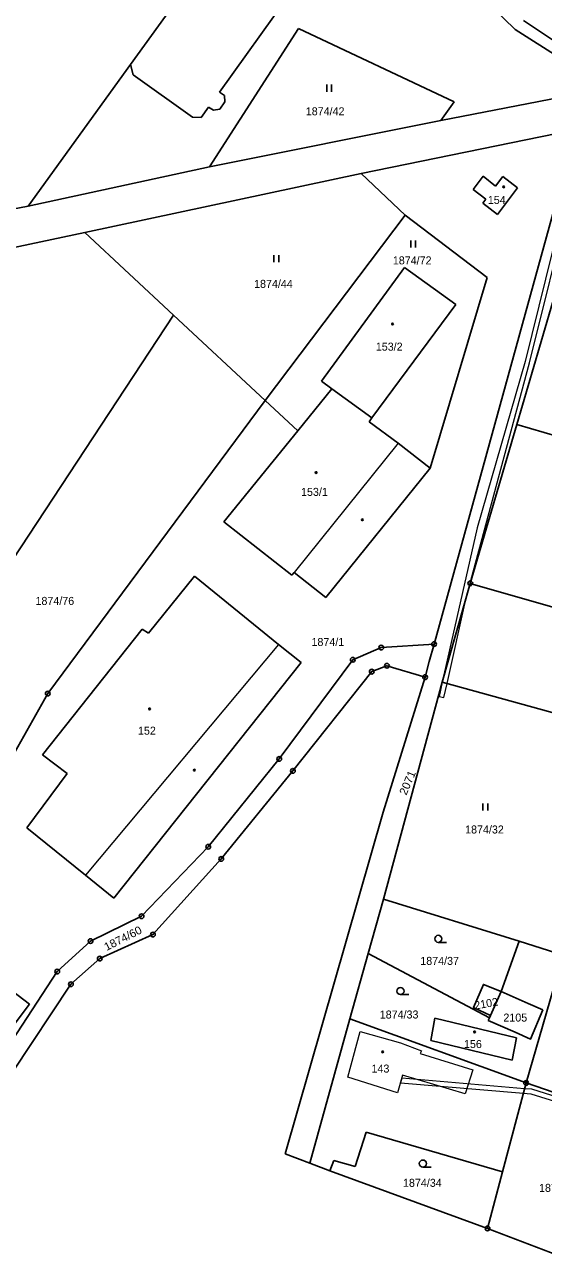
# Model space of a CAD drawing. Extents: x -820420 to -815896, y -1105820 to -1103643.
# Drawn here: x -818234.8 to -818124.5, y -1105443.7 to -1105183.5 of the extents above; entities that cross this region are included whole.
import ezdxf
from ezdxf.enums import TextEntityAlignment as Align

# ---------------------------------------------------------------- set-up
doc = ezdxf.new("R2010")
doc.units = 0
doc.header["$LTSCALE"] = 0.68
for name, color, linetype, lineweight in [('1', 7, 'Continuous', 25), ('13', 7, 'Continuous', 13), ('3', 7, 'Continuous', 25), ('4', 7, 'Continuous', 13), ('5', 7, 'Continuous', 25), ('8', 7, 'Continuous', 25)]:
    doc.layers.add(name, color=color, linetype=linetype, lineweight=lineweight)
doc.layers.add('2', color=7, linetype='Continuous')

msp = doc.modelspace()

# ---------------------------------------------------------------- linework, layer by layer
at = {"layer": '1'}
for p, q in [((-818212.24, -1105192.03), (-818192.32, -1105164.41)), ((-818170.31, -1105165.69), (-818193.33, -1105197.91)), ((-818148.06, -1105167.57), (-818130.53, -1105184.58)), ((-818176.57, -1105184.38), (-818195.46, -1105213.77)), ((-818143.51, -1105199.99), (-818176.57, -1105184.38)), ((-818130.53, -1105184.58), (-818120.64, -1105190.91)), ((-818128.75, -1105182.72), (-818119.23, -1105189.07)), ((-818212.24, -1105192.03), (-818233.95, -1105222.13)), ((-818211.69, -1105194.23), (-818212.24, -1105192.03)), ((-818199.1, -1105203.25), (-818211.69, -1105194.23)), ((-818193.33, -1105197.91), (-818192.28, -1105198.65)), ((-818107.22, -1105196.37), (-818146.34, -1105203.92)), ((-818192.18, -1105200), (-818193.28, -1105201.51)), ((-818192.28, -1105198.65), (-818192.18, -1105200)), ((-818146.34, -1105203.92), (-818143.51, -1105199.99)), ((-818197.25, -1105203.3), (-818199.1, -1105203.25)), ((-818195.66, -1105201.08), (-818197.25, -1105203.3)), ((-818194.63, -1105201.78), (-818195.66, -1105201.08)), ((-818193.28, -1105201.51), (-818194.63, -1105201.78)), ((-818195.46, -1105213.77), (-818146.34, -1105203.92)), ((-818117.64, -1105205.9), (-818163.22, -1105215.2)), ((-818147.77, -1105315.14), (-818117.64, -1105205.9)), ((-818233.95, -1105222.13), (-818195.46, -1105213.77)), ((-818221.95, -1105227.76), (-818163.22, -1105215.2)), ((-818163.22, -1105215.2), (-818153.93, -1105224.05)), ((-818139.45, -1105218.58), (-818137.33, -1105215.73)), ((-818137.33, -1105215.73), (-818134.7, -1105217.89)), ((-818134.7, -1105217.89), (-818133.18, -1105215.87)), ((-818133.18, -1105215.87), (-818130.02, -1105218.25)), ((-818136.79, -1105220.67), (-818139.45, -1105218.58)), ((-818130.02, -1105218.25), (-818134.28, -1105223.91)), ((-818137.44, -1105221.53), (-818136.79, -1105220.67)), ((-818134.28, -1105223.91), (-818137.44, -1105221.53)), ((-818233.95, -1105222.13), (-818290.21, -1105232.95)), ((-818183.63, -1105263.43), (-818153.93, -1105224.05)), ((-818153.93, -1105224.05), (-818136.47, -1105237.29)), ((-818221.95, -1105227.76), (-818256.29, -1105234.97)), ((-818203.09, -1105245.31), (-818221.95, -1105227.76)), ((-818130.15, -1105268.53), (-818119.35, -1105231.56)), ((-818154.01, -1105235.16), (-818171.66, -1105259.34)), ((-818154.01, -1105235.16), (-818143.11, -1105243.04)), ((-818136.47, -1105237.29), (-818148.56, -1105277.82)), ((-818143.11, -1105243.04), (-818160.95, -1105267.11)), ((-818276.5, -1105356.82), (-818203.09, -1105245.31)), ((-818183.63, -1105263.43), (-818203.09, -1105245.31)), ((-818171.66, -1105259.34), (-818169.47, -1105260.93)), ((-818169.47, -1105260.93), (-818176.72, -1105269.85)), ((-818169.47, -1105260.93), (-818160.95, -1105267.11)), ((-818183.63, -1105263.43), (-818229.81, -1105325.68)), ((-818183.63, -1105263.43), (-818176.72, -1105269.85)), ((-818160.95, -1105267.11), (-818161.54, -1105267.93)), ((-818161.54, -1105267.93), (-818155.42, -1105272.47)), ((-818176.72, -1105269.85), (-818192.4, -1105289.16)), ((-818130.15, -1105268.53), (-818140.06, -1105302.25)), ((-818091.29, -1105279.84), (-818130.15, -1105268.53)), ((-818148.56, -1105277.82), (-818155.42, -1105272.47)), ((-818170.77, -1105305.26), (-818148.56, -1105277.82)), ((-818192.4, -1105289.16), (-818177.96, -1105300.5)), ((-818208.38, -1105312.83), (-818198.66, -1105300.72)), ((-818180.79, -1105315.22), (-818198.66, -1105300.72)), ((-818177.96, -1105300.5), (-818177.5, -1105299.92)), ((-818177.5, -1105299.92), (-818170.77, -1105305.26)), ((-818140.06, -1105302.25), (-818146.04, -1105323.26)), ((-818100.68, -1105313.58), (-818140.06, -1105302.25)), ((-818230.93, -1105338.66), (-818209.76, -1105312.01)), ((-818209.76, -1105312.01), (-818208.38, -1105312.83)), ((-818176.02, -1105319.1), (-818180.79, -1105315.22)), ((-818147.77, -1105315.14), (-818158.99, -1105315.89)), ((-818148.83, -1105318.84), (-818147.77, -1105315.14)), ((-818158.99, -1105315.89), (-818165.03, -1105318.49)), ((-818215.76, -1105369.1), (-818176.02, -1105319.1)), ((-818165.03, -1105318.49), (-818180.64, -1105339.54)), ((-818161.01, -1105321.01), (-818157.76, -1105319.76)), ((-818157.76, -1105319.76), (-818149.67, -1105322.18)), ((-818149.67, -1105322.18), (-818148.83, -1105318.84)), ((-818177.74, -1105342.08), (-818161.01, -1105321.01)), ((-818158.55, -1105350.83), (-818149.67, -1105322.18)), ((-818229.81, -1105325.68), (-818254.22, -1105368.94)), ((-818158.52, -1105369.35), (-818146.04, -1105323.26)), ((-818146.04, -1105323.26), (-818117.64, -1105331.07)), ((-818225.72, -1105342.67), (-818230.93, -1105338.66)), ((-818180.64, -1105339.54), (-818195.73, -1105358.2)), ((-818234.23, -1105354.15), (-818225.72, -1105342.67)), ((-818192.96, -1105360.79), (-818177.74, -1105342.08)), ((-818179.38, -1105423.42), (-818158.55, -1105350.83)), ((-818221.76, -1105364.24), (-818234.23, -1105354.15)), ((-818195.73, -1105358.2), (-818209.87, -1105372.95)), ((-818207.47, -1105376.87), (-818192.96, -1105360.79)), ((-818215.76, -1105369.1), (-818221.76, -1105364.24)), ((-818161.75, -1105380.87), (-818158.52, -1105369.35)), ((-818129.72, -1105378.29), (-818158.52, -1105369.35)), ((-818209.87, -1105372.95), (-818220.73, -1105378.25)), ((-818233.66, -1105391.63), (-818253.48, -1105376.62)), ((-818218.78, -1105381.96), (-818207.47, -1105376.87)), ((-818220.73, -1105378.25), (-818227.8, -1105384.72)), ((-818129.72, -1105378.29), (-818133.49, -1105388.97)), ((-818120.31, -1105381.21), (-818129.72, -1105378.29)), ((-818224.88, -1105387.41), (-818218.78, -1105381.96)), ((-818165.66, -1105394.78), (-818161.75, -1105380.87)), ((-818161.75, -1105380.87), (-818136.02, -1105394.57)), ((-818120.31, -1105381.21), (-818128.21, -1105408.38)), ((-818227.8, -1105384.72), (-818240.6, -1105404.25)), ((-818237.33, -1105406.05), (-818224.88, -1105387.41)), ((-818133.49, -1105388.97), (-818135.76, -1105394.05)), ((-818133.49, -1105388.97), (-818127.75, -1105391.5)), ((-818233.66, -1105391.63), (-818261.26, -1105427.85)), ((-818127.75, -1105391.5), (-818124.63, -1105392.83)), ((-818174.15, -1105425.41), (-818165.66, -1105394.78)), ((-818128.21, -1105408.38), (-818165.66, -1105394.78)), ((-818147.59, -1105394.63), (-818148.47, -1105399.36)), ((-818130.23, -1105398.82), (-818147.59, -1105394.63)), ((-818136.27, -1105395.08), (-818136.02, -1105394.57)), ((-818130.55, -1105397.61), (-818136.27, -1105395.08)), ((-818136.02, -1105394.57), (-818135.76, -1105394.05)), ((-818148.47, -1105399.36), (-818131.19, -1105403.55)), ((-818131.19, -1105403.55), (-818130.23, -1105398.82)), ((-818128.21, -1105408.38), (-818133.22, -1105427.25)), ((-818128.21, -1105408.38), (-818090.49, -1105421.23)), ((-818162.15, -1105418.8), (-818164.54, -1105426.12)), ((-818133.22, -1105427.25), (-818162.15, -1105418.8)), ((-818179.38, -1105423.42), (-818174.15, -1105425.41)), ((-818169.93, -1105427.05), (-818174.15, -1105425.41)), ((-818169.08, -1105424.81), (-818169.93, -1105427.05)), ((-818136.41, -1105439.28), (-818169.93, -1105427.05)), ((-818164.54, -1105426.12), (-818169.08, -1105424.81)), ((-818133.22, -1105427.25), (-818136.41, -1105439.28)), ((-818099.7, -1105453.29), (-818136.41, -1105439.28))]:
    msp.add_line(p, q, dxfattribs=at)
for points in [[(-818135.76, -1105394.05), (-818139.41, -1105392.34), (-818137.29, -1105387.45), (-818133.49, -1105388.97)], [(-818124.63, -1105392.83), (-818127.26, -1105399.07), (-818130.55, -1105397.61)]]:
    msp.add_lwpolyline(points, dxfattribs=at)
at = {"layer": '13'}
for points in [[(-818140.93, -1105305.3), (-818127.46, -1105255.4), (-818118.78, -1105220.42), (-818119.76, -1105220.17), (-818128.42, -1105255.14), (-818138.63, -1105290.48), (-818146.04, -1105323.26), (-818145.01, -1105323.54)], [(-818145.67, -1105326.49), (-818145.01, -1105323.54), (-818146.04, -1105323.26), (-818146.65, -1105326.27)], [(-818154.92, -1105408.34), (-818128.79, -1105410.57), (-818128.53, -1105409.59), (-818154.64, -1105407.37)], [(-818128.53, -1105409.59), (-818128.79, -1105410.57), (-818127.23, -1105410.7), (-818090.71, -1105422), (-818090.49, -1105421.23), (-818127.03, -1105409.72)]]:
    msp.add_lwpolyline(points, close=True, dxfattribs=at)
at = {"layer": '3'}
for p, q in [((-818170.571, -1105197.82), (-818170.571, -1105196.32)), ((-818169.57, -1105197.82), (-818169.57, -1105196.32)), ((-818152.681, -1105230.94), (-818152.681, -1105229.44)), ((-818151.68, -1105230.94), (-818151.68, -1105229.44)), ((-818181.761, -1105234.06), (-818181.761, -1105232.56)), ((-818180.76, -1105234.06), (-818180.76, -1105232.56)), ((-818137.371, -1105350.53), (-818137.371, -1105349.03)), ((-818136.37, -1105350.53), (-818136.37, -1105349.03)), ((-818146.873, -1105378.51), (-818145.123, -1105378.51)), ((-818154.893, -1105389.6), (-818153.143, -1105389.6)), ((-818150.143, -1105426.24), (-818148.393, -1105426.24))]:
    msp.add_line(p, q, dxfattribs=at)
for centre in [(-818146.8729, -1105377.7598), (-818154.8929, -1105388.8498), (-818150.1429, -1105425.4898)]:
    msp.add_circle(centre, 0.75, dxfattribs=at)
at = {"layer": '4'}
for p, q in [((-818155.42, -1105272.47), (-818177.5, -1105299.92)), ((-818180.79, -1105315.22), (-818221.76, -1105364.24)), ((-818166.06, -1105407.14), (-818163.43, -1105397.45)), ((-818163.43, -1105397.45), (-818154.86, -1105399.83)), ((-818154.86, -1105399.83), (-818150.42, -1105401.52)), ((-818150.42, -1105401.52), (-818150.68, -1105402.14)), ((-818150.68, -1105402.14), (-818139.54, -1105405.59)), ((-818139.54, -1105405.59), (-818141.13, -1105410.68)), ((-818155.54, -1105410.48), (-818166.06, -1105407.14)), ((-818154.46, -1105406.73), (-818155.54, -1105410.48)), ((-818141.13, -1105410.68), (-818154.46, -1105406.73))]:
    msp.add_line(p, q, dxfattribs=at)
at = {"layer": '5'}
for centre in [(-818132.9868, -1105218.0392), (-818156.5868, -1105247.1592), (-818172.8168, -1105278.7192), (-818163.0068, -1105288.7492), (-818208.1968, -1105328.9192), (-818198.6868, -1105341.9292), (-818139.1668, -1105397.5192), (-818158.6668, -1105401.7792)]:
    msp.add_circle(centre, 0.175, dxfattribs=at)
at = {"layer": '8'}
for centre, radius in [((-818140.06, -1105302.2499), 0.5), ((-818140.06, -1105302.2499), 0.0303), ((-818147.77, -1105315.1399), 0.5), ((-818147.77, -1105315.1399), 0.0303), ((-818158.99, -1105315.8899), 0.5), ((-818158.99, -1105315.8899), 0.0303), ((-818165.03, -1105318.4899), 0.5), ((-818165.03, -1105318.4899), 0.0303), ((-818161.01, -1105321.0099), 0.5), ((-818157.76, -1105319.7599), 0.5), ((-818157.76, -1105319.7599), 0.0303), ((-818161.01, -1105321.0099), 0.0303), ((-818149.67, -1105322.1799), 0.5), ((-818149.67, -1105322.1799), 0.0303), ((-818229.81, -1105325.6799), 0.5), ((-818229.81, -1105325.6799), 0.0303), ((-818180.64, -1105339.5399), 0.5), ((-818180.64, -1105339.5399), 0.0303), ((-818177.74, -1105342.0799), 0.5), ((-818177.74, -1105342.0799), 0.0303), ((-818195.73, -1105358.1999), 0.5), ((-818195.73, -1105358.1999), 0.0303), ((-818192.96, -1105360.7899), 0.5), ((-818192.96, -1105360.7899), 0.0303), ((-818209.87, -1105372.9499), 0.5), ((-818209.87, -1105372.9499), 0.0303), ((-818220.73, -1105378.2499), 0.5), ((-818207.47, -1105376.8699), 0.5), ((-818207.47, -1105376.8699), 0.0303), ((-818220.73, -1105378.2499), 0.0303), ((-818218.78, -1105381.9599), 0.5), ((-818218.78, -1105381.9599), 0.0303), ((-818227.8, -1105384.7199), 0.5), ((-818227.8, -1105384.7199), 0.0303), ((-818224.88, -1105387.4099), 0.5), ((-818224.88, -1105387.4099), 0.0303), ((-818128.21, -1105408.3799), 0.5), ((-818128.21, -1105408.3799), 0.0303), ((-818136.41, -1105439.2799), 0.5), ((-818136.41, -1105439.2799), 0.0303)]:
    msp.add_circle(centre, radius, dxfattribs=at)

# ---------------------------------------------------------------- texts
at = {"layer": '2'}
for s, p in [('1874/42', (-818170.899, -1105202.835)), ('154', (-818134.449, -1105221.665)), ('1874/72', (-818152.409, -1105234.505)), ('1874/44', (-818181.879, -1105239.485)), ('153/2', (-818157.29, -1105252.825)), ('153/1', (-818173.17, -1105283.675)), ('1874/76', (-818228.309, -1105306.835)), ('1874/1', (-818170.32, -1105315.555)), ('152', (-818208.749, -1105334.395)), ('1874/32', (-818137.059, -1105355.385)), ('1874/37', (-818146.579, -1105383.295)), ('1874/33', (-818155.189, -1105394.685)), ('2105', (-818130.51, -1105395.335)), ('156', (-818139.509, -1105400.955)), ('143', (-818159.149, -1105406.165)), ('1874/34', (-818150.249, -1105430.435)), ('1874/30', (-818121.359, -1105431.505))]:
    msp.add_text(s, height=1.7, dxfattribs=at).set_placement(p, align=Align.CENTER)
at = {"layer": '2', "width": 1.05}
for s, rotation, p in [('2071', 67, (-818152.6261, -1105344.9361)), ('1874/60', 27, (-818213.4704, -1105378.4081))]:
    msp.add_text(s, height=1.7, rotation=rotation, dxfattribs=at).set_placement(p, align=Align.CENTER)
at = {"layer": '2'}
msp.add_text('2102', height=1.7, rotation=10, dxfattribs=at).set_placement((-818136.5506, -1105392.3449), align=Align.CENTER)

doc.saveas('drawing.dxf')
